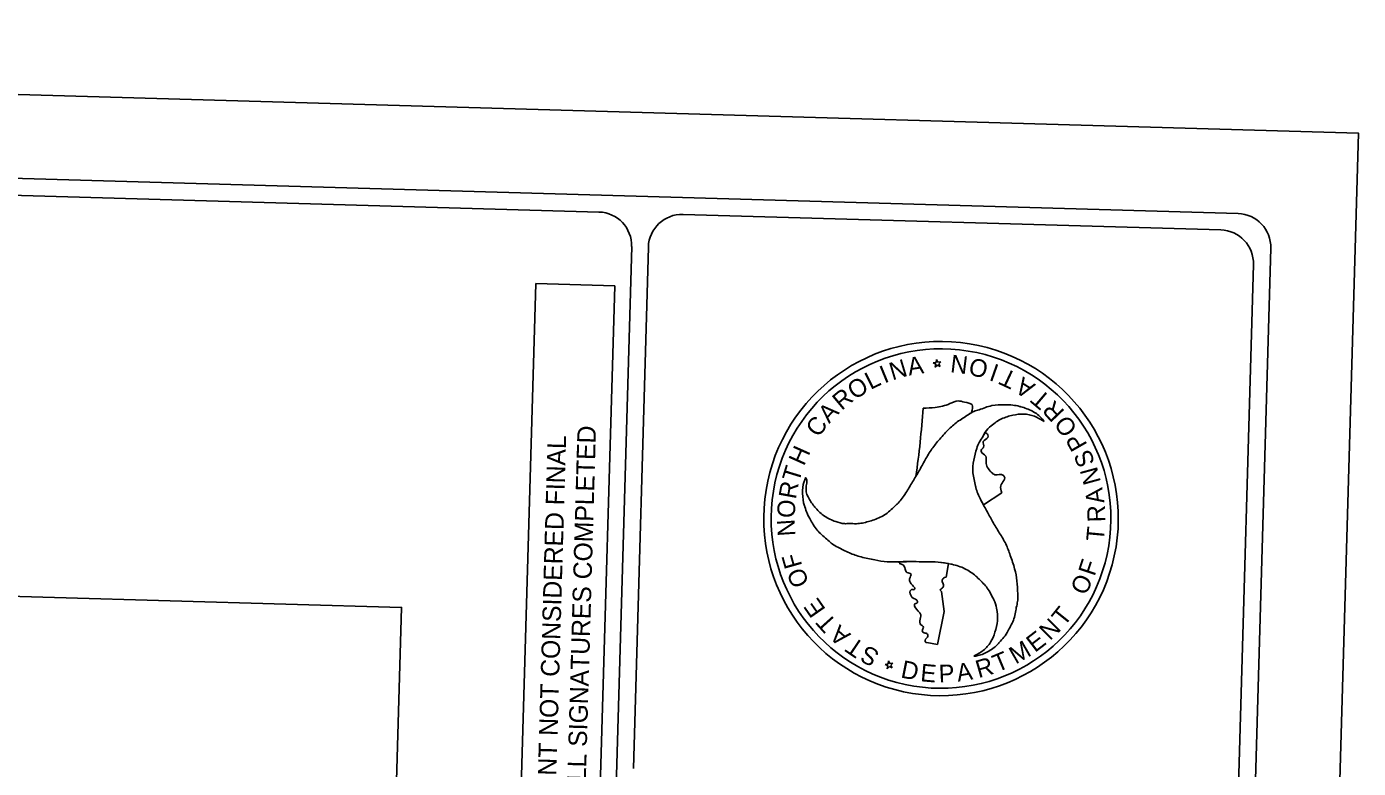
# Model space of a CAD drawing. Extents: x 2097846 to 2099709, y 989477 to 992073.
# Drawn here: x 2098974 to 2099568, y 991742 to 992073 of the extents above; entities that cross this region are included whole.
import ezdxf

# ---------------------------------------------------------------- set-up
doc = ezdxf.new("R2010")
doc.units = 0
for name, color, linetype in [('Sheet Sticker Exception Certification CELL', 7, 'Continuous'), ('Sheet Title CELL', 7, 'Continuous'), ('Stewart Plot Border Xerox6279 and LJ5000', 7, 'Continuous')]:
    doc.layers.add(name, color=color, linetype=linetype)

msp = doc.modelspace()

# ---------------------------------------------------------------- linework, layer by layer
at = {"layer": 'Sheet Sticker Exception Certification CELL'}
for p, q in [((2099192.91, 991658.64), (2099201.55, 991958.57)), ((2099201.57, 991958.57), (2099236.81, 991957.55)), ((2099236.79, 991957.56), (2099228.15, 991657.62))]:
    msp.add_line(p, q, dxfattribs=at)
at = {"layer": 'Sheet Title CELL'}
for p, q in [((2099183.04, 989845.97), (2099244.37, 991975.08)), ((2099245.16, 991742.12), (2099251.87, 991974.87)), ((2099394.99, 991931.71), (2099394.99, 991931.71)), ((2099380.1, 991923.39), (2099378.78, 991923.13)), ((2099378.78, 991923.13), (2099379.96, 991922.51)), ((2099379.96, 991922.51), (2099379.74, 991921.17)), ((2099380.27, 991924.72), (2099380.1, 991923.39)), ((2099380.93, 991923.5), (2099380.27, 991924.72)), ((2099382.29, 991923.68), (2099380.93, 991923.5)), ((2099381.33, 991922.72), (2099382.29, 991923.68)), ((2099381.94, 991921.55), (2099381.33, 991922.72)), ((2099379.74, 991921.17), (2099380.71, 991922.15)), ((2099380.71, 991922.15), (2099381.94, 991921.55)), ((2099321.84, 991871.98), (2099321.98, 991871.81)), ((2099321.84, 991871.98), (2099321.98, 991871.81)), ((2099371.13, 991872.54), (2099371.13, 991872.54)), ((2099409.4, 991865.18), (2099401.23, 991859.79)), ((2099401.23, 991859.79), (2099401.23, 991859.79)), ((2099385.68, 991833.61), (2099384.6, 991827.44)), ((2099382.57, 991821.08), (2099383.69, 991812.18)), ((2099383.69, 991812.18), (2099380.73, 991797.47)), ((2099380.73, 991797.47), (2099376.06, 991798.39)), ((2099357.36, 991788.56), (2099358.69, 991788.82)), ((2099358.55, 991787.99), (2099357.36, 991788.56)), ((2099358.33, 991786.62), (2099358.55, 991787.99)), ((2099359.32, 991787.58), (2099358.33, 991786.62)), ((2099358.69, 991788.82), (2099358.91, 991790.16)), ((2099358.91, 991790.16), (2099359.54, 991788.92)), ((2099360.55, 991786.97), (2099359.32, 991787.58)), ((2099359.54, 991788.92), (2099360.9, 991789.12)), ((2099360.9, 991789.12), (2099359.91, 991788.15)), ((2099359.91, 991788.15), (2099360.55, 991786.97))]:
    msp.add_line(p, q, dxfattribs=at)
for points in [[(2099514.91, 991989.8), (2097970.56, 992034.29)], [(2099229.83, 991990.51), (2097977.83, 992026.57)], [(2099507.19, 991982.52), (2099267.29, 991989.43)], [(2099465.57, 989755.3), (2099529.49, 991974.37)], [(2099515.05, 991734.35), (2099521.75, 991967.09)], [(2098625.54, 991828.82), (2099141.74, 991813.95), (2099102.18, 990440.79), (2098609.99, 990454.98)]]:
    msp.add_lwpolyline(points, dxfattribs=at)
for centre, radius, start, end in [((2099229.31, 991975.52), 15, 358.35004, 88.35004), ((2099266.79, 991974.44), 15, 88.35004, 178.35004), ((2099514.41, 991974.82), 15, 358.35004, 88.35004), ((2099506.69, 991967.53), 15, 358.35004, 88.35004), ((2099382.33, 991853.66), 79.08, 80.77069, 260.77069), ((2099382.33, 991853.66), 75.78, 80.77069, 260.77069), ((2099382.33, 991853.66), 79.07, 260.77069, 80.77069), ((2099382.33, 991853.66), 75.78, 260.77069, 80.77069), ((2098958.38, 991931.37), 416.92, 351.88824, 356.09425), ((2098958.38, 991931.37), 416.92, 346.44918, 346.54878)]:
    msp.add_arc(centre, radius, start, end, dxfattribs=at)
for points in [[(2099428.38, 991896.93), (2099427.32, 991898.34), (2099423.12, 991901.54), (2099417.9, 991903.6), (2099417.38, 991903.75), (2099414.4, 991904.28), (2099410.84, 991904.46), (2099404.96, 991904.08), (2099399.29, 991902.23), (2099396.91, 991901.45), (2099394.47, 991900), (2099389.6, 991896.8), (2099385.48, 991893.22), (2099381.26, 991888.54), (2099377.86, 991884.17), (2099374.92, 991879.21), (2099372.11, 991874.21), (2099369.27, 991869.45), (2099366.23, 991864.46), (2099362.7, 991860.11), (2099362.33, 991859.77), (2099357.73, 991855.67), (2099352.5, 991853.15), (2099347.29, 991851.67), (2099344.61, 991851.35), (2099341.22, 991851.42), (2099339.27, 991851.38), (2099335.38, 991852.3), (2099330.34, 991854.73), (2099326.48, 991858.28), (2099323.62, 991862.19), (2099322.1, 991866.88), (2099321.98, 991871.81), (2099321.84, 991871.98)], [(2099374.34, 991902.96), (2099379.72, 991903.22), (2099386.3, 991904.96), (2099389.94, 991906.17), (2099392.82, 991905.65), (2099396.16, 991904.42), (2099395.97, 991901.03)], [(2099395.99, 991901.01), (2099394.47, 991900), (2099389.6, 991896.8), (2099385.48, 991893.22), (2099381.26, 991888.54), (2099377.86, 991884.17), (2099374.92, 991879.21), (2099372.11, 991874.21), (2099371.13, 991872.54)], [(2099396.89, 991792.18), (2099398.74, 991792.45), (2099403.59, 991794.49), (2099408, 991797.95), (2099408.3, 991798.35), (2099410.36, 991800.65), (2099412.22, 991803.63), (2099414.84, 991808.95), (2099416.07, 991814.73), (2099416.58, 991817.19), (2099416.54, 991820.12), (2099416.18, 991825.83), (2099415.17, 991831.17), (2099413.24, 991837.23), (2099411.19, 991842.31), (2099408.33, 991847.33), (2099405.35, 991852.28), (2099402.66, 991857.18), (2099399.95, 991862.25), (2099397.88, 991867.51), (2099397.76, 991868.07), (2099396.55, 991874.06), (2099396.95, 991879.79), (2099398.27, 991884.99), (2099399.3, 991887.65), (2099401.1, 991890.42), (2099402.03, 991892.19), (2099404.76, 991895.09), (2099409.37, 991898.17), (2099414.38, 991899.78), (2099419.24, 991900.32), (2099424.04, 991899.3), (2099428.38, 991896.93)], [(2099401.23, 991859.79), (2099399.95, 991862.25), (2099397.88, 991867.51), (2099397.76, 991868.07), (2099396.55, 991874.06), (2099396.95, 991879.79), (2099398.27, 991884.99), (2099399.3, 991887.65), (2099401.1, 991890.42), (2099401.99, 991892.05)], [(2099402.01, 991892.03), (2099403.25, 991891.09), (2099403.16, 991889.89), (2099401.18, 991888.1), (2099401.28, 991885.5), (2099400.42, 991884.45), (2099400.27, 991883.69), (2099402.27, 991881.49), (2099402.41, 991878.9), (2099404.74, 991874.37), (2099406.34, 991873.25), (2099410.14, 991872.95), (2099410.72, 991871.83), (2099410.34, 991870.66), (2099408.96, 991868.32), (2099409.4, 991865.18)], [(2099321.98, 991871.81), (2099321.23, 991870.13), (2099320.6, 991864.91), (2099321.43, 991859.36), (2099321.61, 991858.86), (2099322.57, 991856), (2099324.19, 991852.86), (2099327.51, 991847.98), (2099331.91, 991843.94), (2099333.8, 991842.3), (2099336.24, 991840.93), (2099341.46, 991838.3), (2099346.64, 991836.53), (2099352.81, 991835.18), (2099358.28, 991834.38), (2099364, 991834.38), (2099369.78, 991834.43), (2099375.37, 991834.36), (2099381.12, 991834.21), (2099386.7, 991833.32), (2099387.18, 991833.22), (2099392.96, 991831.26), (2099397.78, 991828.01), (2099401.65, 991824.2), (2099403.36, 991822.04), (2099404.97, 991819.1), (2099405.91, 991817.43), (2099407.14, 991813.59), (2099407.52, 991808.05), (2099406.37, 991802.87), (2099404.44, 991798.43), (2099401.17, 991794.79), (2099396.89, 991792.18)], [(2099376.06, 991798.39), (2099375.59, 991798.3), (2099375.21, 991799.17), (2099376.47, 991801.22), (2099375.7, 991802.49), (2099374.75, 991802.59), (2099373.94, 991803.63), (2099374.49, 991805.08), (2099372.97, 991806.73), (2099372.88, 991808.03), (2099373.3, 991810.66), (2099370.67, 991814.3), (2099370.69, 991815.65), (2099371.58, 991815.84), (2099371.87, 991816.62), (2099369.5, 991818.38), (2099369.19, 991818.79), (2099368.61, 991821.4), (2099369.18, 991821.97), (2099370.37, 991821.97), (2099370.66, 991822.28), (2099370.21, 991823.18), (2099369, 991824.49), (2099368.28, 991826.68), (2099368.93, 991828.92), (2099367.12, 991829.62), (2099365.76, 991832.6), (2099364.76, 991833.33), (2099363.67, 991833.65)], [(2099363.86, 991834.38), (2099364, 991834.38), (2099369.78, 991834.43), (2099375.37, 991834.36), (2099381.12, 991834.21), (2099385.67, 991833.59)], [(2099384.6, 991827.44), (2099383.37, 991827.03), (2099382.83, 991825.88), (2099383.42, 991824.12), (2099383.15, 991822.91), (2099381.96, 991821.72), (2099382.57, 991821.08)]]:
    msp.add_spline(points, degree=3, dxfattribs=at)
at = {"layer": 'Stewart Plot Border Xerox6279 and LJ5000'}
msp.add_lwpolyline([(2099495.04, 989476.82), (2099568.48, 992025.76), (2097919.17, 992073.28), (2097845.72, 989524.34)], close=True, dxfattribs=at)

# ---------------------------------------------------------------- texts
at = {"layer": 'Sheet Sticker Exception Certification CELL'}
for s, p in [('UNLESS ALL SIGNATURES COMPLETED', (2099222.31, 991681.8)), ('DOCUMENT NOT CONSIDERED FINAL', (2099209.33, 991689.78))]:
    msp.add_text(s, height=8.25, rotation=88.34956, dxfattribs=at).set_placement(p)
at = {"layer": 'Sheet Title CELL'}
for s, height, rotation, p in [('N', 7.88, 16.66603, (2099360.63, 991915.3)), ('A', 7.89, 9.23405, (2099368.05, 991917.47)), ('N', 7.89, 172.97882, (2099394.72, 991925.93)), ('O', 7.86, 165.73081, (2099403.97, 991923.67)), ('I', 7.9, 160.59518, (2099408.76, 991922.04)), ('L', 7.86, 26.35547, (2099350.88, 991911)), ('I', 7.9, 22.36613, (2099357.05, 991913.89)), ('T', 7.87, 154.94527, (2099416.84, 991918.3)), ('A', 7.9, 147.86085, (2099424.81, 991913.42)), ('R', 7.88, 39.70875, (2099337.99, 991901.67)), ('O', 7.9, 32.58915, (2099343.8, 991906.47)), ('T', 7.86, 139.77381, (2099431.73, 991907.76)), ('R', 7.9, 133.67402, (2099437.84, 991901.52)), ('C', 7.86, 53.56973, (2099327.68, 991889.53)), ('A', 7.88, 46.0727, (2099332.39, 991895.84)), ('O', 7.9, 126.48491, (2099443.55, 991893.9)), ('P', 7.88, 119.79292, (2099447.81, 991886.6)), ('H', 7.87, 65.91208, (2099321.2, 991876.81)), ('S', 7.85, 112.60107, (2099451.2, 991878.57)), ('T', 7.9, 72.9968, (2099318.89, 991869.44)), ('N', 7.86, 105.3906, (2099453.73, 991870.02)), ('R', 7.89, 79.64643, (2099317.54, 991862.02)), ('A', 7.86, 98.35897, (2099455.23, 991860.82)), ('O', 7.9, 86.25636, (2099316.99, 991853.7)), ('R', 7.89, 91.60584, (2099455.6, 991852.12)), ('N', 7.89, 93.75447, (2099317.45, 991846)), ('T', 7.86, 84.64922, (2099454.86, 991843.22)), ('F', 7.9, 105.84141, (2099320.48, 991832.62)), ('F', 7.88, 71.73999, (2099450.81, 991827.61)), ('O', 7.89, 112.98825, (2099323.69, 991824.92)), ('O', 7.88, 64.57476, (2099446.83, 991818.95)), ('E', 7.86, 124.92763, (2099331.12, 991813.08)), ('T', 7.87, 132.04326, (2099336.27, 991807.33)), ('T', 7.87, 51.27107, (2099437.21, 991805.15)), ('A', 7.91, 139.09848, (2099342.43, 991801.98)), ('E', 7.86, 37.45753, (2099424.22, 991793.61)), ('N', 7.9, 44.42907, (2099430.91, 991798.86)), ('T', 7.9, 146.15079, (2099348.77, 991797.6)), ('M', 7.86, 29.99076, (2099415.62, 991788.45)), ('S', 7.88, 152.52694, (2099355.42, 991794.12)), ('T', 7.88, 22.75572, (2099407.41, 991784.87)), ('D', 7.89, 348.62369, (2099364.02, 991782.75)), ('E', 7.85, 354.91158, (2099372.91, 991781.05)), ('P', 7.89, 2.44397, (2099381.45, 991780.44)), ('A', 7.87, 9.03655, (2099389.87, 991780.81)), ('R', 7.88, 16.10518, (2099399.08, 991782.37))]:
    msp.add_text(s, height=height, rotation=rotation, dxfattribs=at).set_placement(p)

doc.saveas('drawing.dxf')
